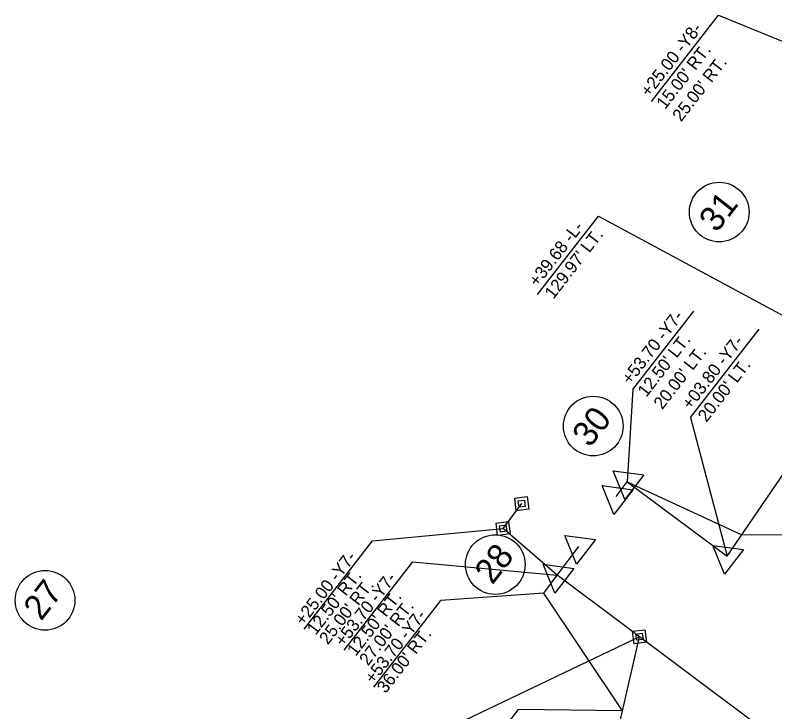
# Model space of a CAD drawing. Extents: x 2010883 to 2014849, y 442000 to 447413.
# Drawn here: x 2014094.3 to 2014399.8, y 445727.9 to 446008.1 of the extents above; entities that cross this region are included whole.
import ezdxf

# ---------------------------------------------------------------- set-up
doc = ezdxf.new("R2010")
doc.units = 0
for name, color, linetype in [('Prop Easement Construction', 7, 'Continuous'), ('Prop Easement Construction Station Offsets', 7, 'Continuous'), ('Prop Easement Permanent Drainage Utility', 7, 'Continuous'), ('Prop Easement Permanent Drainage Utility Station Offsets', 7, 'Continuous'), ('Prop Easement Permanent Utility', 7, 'Continuous'), ('Prop Easement Permanent Utility Station Offsets', 7, 'Continuous'), ('Prop Parcel Number CELL', 7, 'Continuous'), ('Prop Parcel Number Text', 7, 'Continuous'), ('Prop ROW Marker CELL', 7, 'Continuous'), ('Prop ROW Permanent Easement CELL', 7, 'Continuous'), ('Prop ROW RW Lines', 7, 'Continuous'), ('Prop ROW Station Offsets', 7, 'Continuous')]:
    doc.layers.add(name, color=color, linetype=linetype)

msp = doc.modelspace()

# ---------------------------------------------------------------- linework, layer by layer
at = {"layer": 'Prop Easement Construction'}
for p, q in [((2014340.45, 445820.48), (2014386.46, 445799.12)), ((2014306.89, 445775.65), (2014312.29, 445782.85)), ((2014338.51, 445728.25), (2014306.89, 445775.65))]:
    msp.add_line(p, q, dxfattribs=at)
at = {"layer": 'Prop Easement Construction Station Offsets'}
for p, q in [((2014386.46, 445799.12), (2014450.66, 445799.63)), ((2014306.89, 445775.65), (2014265.45, 445772.62)), ((2014238.48, 445737.85), (2014265.45, 445772.62)), ((2014269.69, 445694.09), (2014296.66, 445728.85)), ((2014338.51, 445728.25), (2014296.66, 445728.85))]:
    msp.add_line(p, q, dxfattribs=at)
at = {"layer": 'Prop Easement Permanent Drainage Utility'}
msp.add_line((2014308.73, 445598.23), (2014345.35, 445758.1), dxfattribs=at)
at = {"layer": 'Prop Easement Permanent Drainage Utility Station Offsets'}
msp.add_line((2014345.35, 445758.1), (2014274.92, 445724.48), dxfattribs=at)
at = {"layer": 'Prop Easement Permanent Utility'}
for p, q in [((2014290.51, 445801.65), (2014298, 445811.66)), ((2014312.29, 445782.85), (2014290.51, 445801.65))]:
    msp.add_line(p, q, dxfattribs=at)
at = {"layer": 'Prop Easement Permanent Utility Station Offsets'}
for p, q in [((2014238.03, 445796.72), (2014290.51, 445801.65)), ((2014210.45, 445761.16), (2014238.03, 445796.72))]:
    msp.add_line(p, q, dxfattribs=at)
at = {"layer": 'Prop Parcel Number CELL'}
for p, q in [((2014377.41, 445928.93), (2014377.41, 445928.93)), ((2014326.76, 445842.86), (2014326.76, 445842.86)), ((2014287.34, 445787.13), (2014287.34, 445787.13)), ((2014106.26, 445772.75), (2014106.26, 445772.75))]:
    msp.add_line(p, q, dxfattribs=at)
for centre in [(2014377.41, 445928.93), (2014326.76, 445842.86), (2014287.34, 445787.13), (2014106.26, 445772.75)]:
    msp.add_circle(centre, 12, dxfattribs=at)
at = {"layer": 'Prop ROW Marker CELL'}
for p, q in [((2014340.45, 445820.48), (2014340.45, 445820.48)), ((2014335.96, 445814.47), (2014335.96, 445814.47)), ((2014298, 445811.66), (2014298, 445811.66)), ((2014290.51, 445801.65), (2014290.51, 445801.65)), ((2014320.98, 445794.46), (2014320.98, 445794.46)), ((2014380.56, 445790.46), (2014380.56, 445790.46)), ((2014312.29, 445782.85), (2014312.29, 445782.85)), ((2014345.35, 445758.1), (2014345.35, 445758.1))]:
    msp.add_line(p, q, dxfattribs=at)
for points in [[(2014339.46, 445813.33), (2014334.76, 445824.89), (2014347.13, 445823.21)], [(2014334.97, 445807.33), (2014330.27, 445818.88), (2014342.63, 445817.21)], [(2014319.99, 445787.31), (2014315.29, 445798.87), (2014327.65, 445797.19)], [(2014379.57, 445783.32), (2014374.87, 445794.87), (2014387.23, 445793.19)], [(2014311.3, 445775.7), (2014306.6, 445787.26), (2014318.96, 445785.58)]]:
    msp.add_lwpolyline(points, close=True, dxfattribs=at)
at = {"layer": 'Prop ROW Permanent Easement CELL'}
for points in [[(2014295.15, 445813.86), (2014300.2, 445814.5), (2014300.84, 445809.45), (2014295.79, 445808.81)], [(2014296.57, 445812.76), (2014299.1, 445813.08), (2014299.42, 445810.55), (2014296.89, 445810.23)], [(2014287.66, 445803.85), (2014292.71, 445804.49), (2014293.35, 445799.44), (2014288.3, 445798.8)], [(2014289.08, 445802.75), (2014291.61, 445803.07), (2014291.93, 445800.55), (2014289.4, 445800.23)], [(2014342.51, 445760.31), (2014347.56, 445760.95), (2014348.2, 445755.9), (2014343.14, 445755.26)], [(2014343.93, 445759.21), (2014346.45, 445759.53), (2014346.77, 445757), (2014344.25, 445756.68)]]:
    msp.add_lwpolyline(points, close=True, dxfattribs=at)
at = {"layer": 'Prop ROW RW Lines'}
for p, q in [((2014380.56, 445790.46), (2014434.87, 445870.16)), ((2014335.96, 445814.47), (2014340.45, 445820.48)), ((2014340.45, 445820.48), (2014380.56, 445790.46)), ((2014312.29, 445782.85), (2014320.98, 445794.46)), ((2014391.79, 445723.35), (2014312.29, 445782.85))]:
    msp.add_line(p, q, dxfattribs=at)
at = {"layer": 'Prop ROW Station Offsets'}
for p, q in [((2014350.18, 445973.36), (2014377.15, 446008.13)), ((2014377.15, 446008.13), (2014448.82, 445978.88)), ((2014304.32, 445895.72), (2014328.83, 445927.32)), ((2014328.83, 445927.32), (2014434.87, 445870.16)), ((2014342.69, 445857.5), (2014367.2, 445889.11)), ((2014365.9, 445846.27), (2014393.48, 445881.83)), ((2014342.69, 445857.5), (2014340.45, 445820.48)), ((2014365.9, 445846.27), (2014380.56, 445790.46)), ((2014226.57, 445752.68), (2014254.15, 445788.24)), ((2014254.15, 445788.24), (2014312.29, 445782.85))]:
    msp.add_line(p, q, dxfattribs=at)

# ---------------------------------------------------------------- texts
at = {"layer": 'Prop Easement Construction Station Offsets'}
for s, p in [('+53.70 -Y7-', (2014238.28, 445738.86)), ("36.00' RT.", (2014243.22, 445735.03))]:
    msp.add_text(s, height=5, rotation=52.2051, dxfattribs=at).set_placement(p)
at = {"layer": 'Prop Easement Permanent Utility Station Offsets'}
for s, p in [('+25.00 -Y7-', (2014210.16, 445762.3)), ("12.50' RT.", (2014215.1, 445758.47)), ("25.00' RT.", (2014220.04, 445754.64))]:
    msp.add_text(s, height=5, rotation=52.2051, dxfattribs=at).set_placement(p)
at = {"layer": 'Prop Parcel Number Text'}
for s, p in [('31', (2014376.39, 445920.31)), ('30', (2014325.41, 445833.84)), ('28', (2014286.17, 445778.69)), ('27', (2014104.71, 445764.15))]:
    msp.add_text(s, height=10, rotation=52.2051, dxfattribs=at).set_placement(p)
at = {"layer": 'Prop ROW Station Offsets'}
for s, p in [('+25.00 -Y8-', (2014349.22, 445974.93)), ("15.00' RT.", (2014355.64, 445969.95)), ("25.00' RT.", (2014362.06, 445964.97)), ('+39.68 -L-', (2014304.29, 445898.58)), ("129.97' LT.", (2014310.71, 445893.6)), ('+53.70 -Y7-', (2014341.68, 445859.2)), ("12.50' LT.", (2014348.11, 445854.22)), ('+03.80 -Y7-', (2014365.88, 445849.13)), ("20.00' LT.", (2014354.53, 445849.24)), ("20.00' LT.", (2014372.3, 445844.15)), ('+53.70 -Y7-', (2014226.28, 445753.82)), ("12.50' RT.", (2014231.22, 445749.99)), ("27.00' RT.", (2014236.16, 445746.16))]:
    msp.add_text(s, height=5, rotation=52.2051, dxfattribs=at).set_placement(p)

doc.saveas('drawing.dxf')
